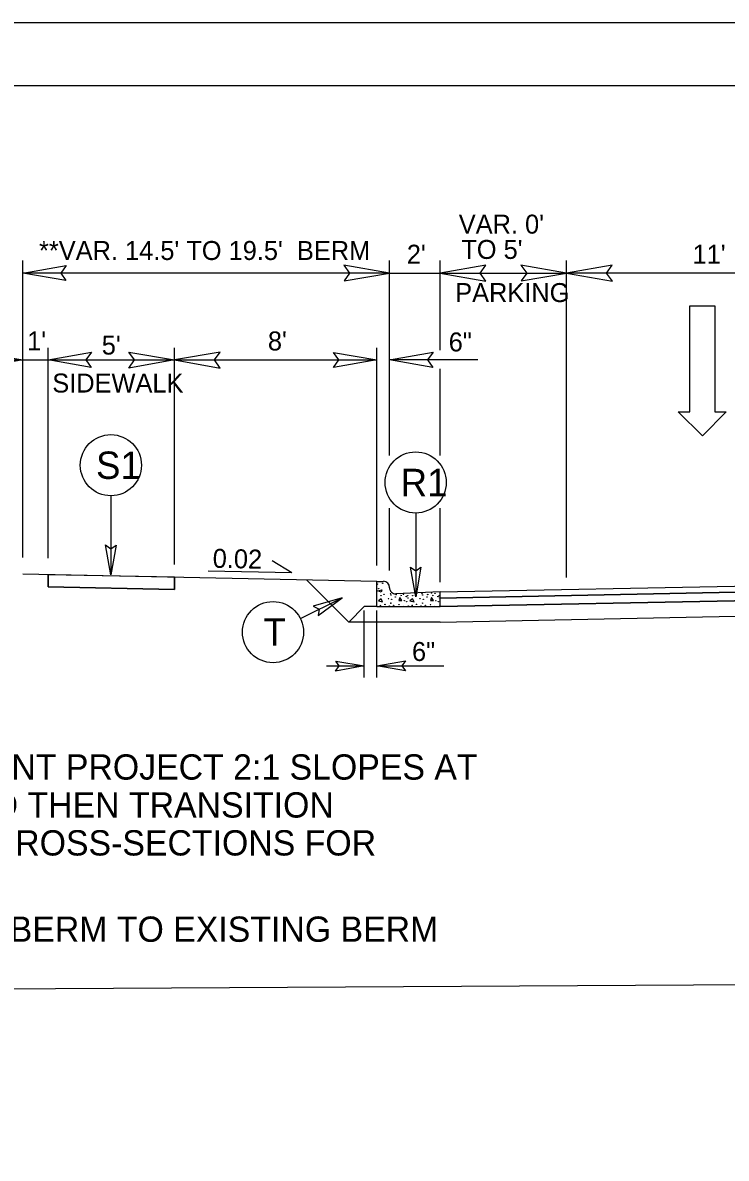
# Model space of a CAD drawing. Extents: x 1487909 to 1489267, y 497866 to 499814.
# Drawn here: x 1488931.46 to 1488959.27, y 498292.62 to 498337.52 of the extents above; entities that cross this region are included whole.
import ezdxf

# ---------------------------------------------------------------- set-up
doc = ezdxf.new("R2010")
doc.units = 0
for name, color, linetype in [('Old_Level_10', 7, 'Continuous'), ('Prop Conc 4in Sidewalk', 7, 'Continuous'), ('Prop Dimension', 7, 'Continuous'), ('Prop Dimension Text', 7, 'Continuous'), ('Prop DSN Text', 7, 'Continuous'), ('Prop Lane Arrow CELL', 7, 'Continuous'), ('Prop Shade Light', 7, 'Continuous'), ('Prop Terminator CELL', 7, 'Continuous'), ('Scratch_Level_1', 7, 'Continuous'), ('Sheet Plot Border Outside CELL', 7, 'Continuous'), ('Sheet Typical CELL', 7, 'Continuous'), ('Typical Curb CELL', 7, 'Continuous'), ('Typical Hinge Slope Arterial CELL', 7, 'Continuous'), ('Typical ID Circle CELL', 7, 'Continuous'), ('Typical Pavement Slope CELL', 7, 'Continuous'), ('Typical Pavement Slope Information CELL', 7, 'Continuous'), ('Typical Terminator CELL', 7, 'Continuous'), ('Typical Text ID Circle CELL', 7, 'Continuous')]:
    doc.layers.add(name, color=color, linetype=linetype)

msp = doc.modelspace()

# ---------------------------------------------------------------- linework, layer by layer
at = {"layer": 'Old_Level_10'}
for p, q in [((1488947.963, 498314.766), (1488974.964, 498315.306)), ((1488967.463, 498314.823), (1488947.963, 498314.433)), ((1488947.963, 498314.433), (1488947.963, 498314.766))]:
    msp.add_line(p, q, dxfattribs=at)
at = {"layer": 'Prop Conc 4in Sidewalk'}
for p, q in [((1488937.464, 498315.593), (1488932.464, 498315.693)), ((1488932.464, 498315.212), (1488932.464, 498315.693)), ((1488937.464, 498315.112), (1488932.464, 498315.212)), ((1488937.464, 498315.593), (1488937.464, 498315.112))]:
    msp.add_line(p, q, dxfattribs=at)
at = {"layer": 'Prop Dimension'}
for p, q in [((1488931.464, 498316.375), (1488931.464, 498328.119)), ((1488945.964, 498320.407), (1488945.964, 498328.119)), ((1488947.964, 498324.577), (1488947.964, 498328.119)), ((1488952.964, 498315.587), (1488952.964, 498328.119)), ((1488945.964, 498327.619), (1488931.464, 498327.619)), ((1488945.964, 498327.619), (1488947.964, 498327.619)), ((1488947.964, 498327.619), (1488952.964, 498327.619)), ((1488963.964, 498327.619), (1488952.964, 498327.619)), ((1488932.464, 498316.345), (1488932.464, 498324.66)), ((1488937.464, 498316.097), (1488937.464, 498324.66)), ((1488945.464, 498316.054), (1488945.464, 498324.66)), ((1488929.133, 498324.188), (1488931.464, 498324.188)), ((1488931.464, 498324.188), (1488932.464, 498324.188)), ((1488932.464, 498324.188), (1488937.464, 498324.188)), ((1488937.464, 498324.188), (1488945.464, 498324.188)), ((1488949.459, 498324.188), (1488945.964, 498324.188)), ((1488947.964, 498320.407), (1488947.964, 498323.84)), ((1488945.964, 498315.857), (1488945.964, 498318.327)), ((1488947.964, 498315.395), (1488947.964, 498318.327))]:
    msp.add_line(p, q, dxfattribs=at)
at = {"layer": 'Prop DSN Text'}
for p, q in [((1488944.964, 498311.627), (1488944.964, 498314.281)), ((1488945.464, 498311.627), (1488945.464, 498314.281)), ((1488943.477, 498312.087), (1488944.964, 498312.087)), ((1488945.464, 498312.087), (1488948.112, 498312.087))]:
    msp.add_line(p, q, dxfattribs=at)
at = {"layer": 'Prop Lane Arrow CELL'}
for p, q in [((1488957.827, 498322.131), (1488957.827, 498326.331)), ((1488957.827, 498326.331), (1488958.817, 498326.331)), ((1488958.817, 498326.331), (1488958.817, 498322.131)), ((1488958.337, 498321.186), (1488957.377, 498322.131)), ((1488957.377, 498322.131), (1488957.827, 498322.131)), ((1488959.267, 498322.131), (1488958.337, 498321.186)), ((1488958.817, 498322.131), (1488959.267, 498322.131))]:
    msp.add_line(p, q, dxfattribs=at)
at = {"layer": 'Prop Shade Light'}
for p, q in [((1488937.464, 498315.593), (1488932.464, 498315.693)), ((1488932.464, 498315.693), (1488932.464, 498315.212)), ((1488932.464, 498315.212), (1488937.464, 498315.112)), ((1488937.464, 498315.112), (1488937.464, 498315.593)), ((1488947.963, 498315.016), (1488974.964, 498315.556)), ((1488974.964, 498315.306), (1488947.963, 498314.766)), ((1488947.963, 498314.766), (1488947.963, 498315.016))]:
    msp.add_line(p, q, dxfattribs=at)
at = {"layer": 'Prop Terminator CELL'}
for points in [[(1488933.174, 498327.324), (1488931.464, 498327.619), (1488933.183, 498327.923), (1488932.965, 498327.619)], [(1488944.164, 498327.309), (1488945.964, 498327.619), (1488944.154, 498327.939), (1488944.384, 498327.619)], [(1488949.764, 498327.929), (1488947.964, 498327.619), (1488949.774, 498327.299), (1488949.544, 498327.619)], [(1488951.164, 498327.309), (1488952.964, 498327.619), (1488951.154, 498327.939), (1488951.384, 498327.619)], [(1488954.764, 498327.929), (1488952.964, 498327.619), (1488954.774, 498327.299), (1488954.544, 498327.619)], [(1488929.664, 498324.498), (1488931.464, 498324.188), (1488929.654, 498323.868), (1488929.884, 498324.188)], [(1488934.174, 498323.894), (1488932.464, 498324.188), (1488934.183, 498324.492), (1488933.965, 498324.188)], [(1488935.664, 498324.498), (1488937.464, 498324.188), (1488935.654, 498323.868), (1488935.884, 498324.188)], [(1488939.264, 498324.498), (1488937.464, 498324.188), (1488939.274, 498323.868), (1488939.044, 498324.188)], [(1488943.754, 498324.483), (1488945.464, 498324.188), (1488943.744, 498323.884), (1488943.963, 498324.188)], [(1488947.674, 498323.894), (1488945.964, 498324.188), (1488947.683, 498324.492), (1488947.465, 498324.188)]]:
    msp.add_lwpolyline(points, close=True, dxfattribs=at)
at = {"layer": 'Scratch_Level_1'}
msp.add_line((1488899.964, 498299.145), (1489049.964, 498300.02), dxfattribs=at)
at = {"layer": 'Sheet Plot Border Outside CELL'}
msp.add_lwpolyline([(1489051.664, 498337.52), (1488883.264, 498337.52), (1488883.264, 498227.52), (1489051.664, 498227.52)], close=True, dxfattribs=at)
at = {"layer": 'Sheet Typical CELL'}
msp.add_lwpolyline([(1489049.964, 498335.02), (1488899.964, 498335.02), (1488899.964, 498230.02), (1489049.964, 498230.02)], close=True, dxfattribs=at)
at = {"layer": 'Typical Curb CELL'}
for p, q in [((1488945.464, 498314.433), (1488945.464, 498315.433)), ((1488945.464, 498315.433), (1488945.724, 498315.433)), ((1488945.964, 498315.183), (1488945.964, 498315.194)), ((1488945.5, 498315.055), (1488945.654, 498315.1)), ((1488945.638, 498315.009), (1488945.5, 498315.055)), ((1488945.626, 498314.736), (1488945.523, 498314.661)), ((1488945.689, 498314.622), (1488945.626, 498314.736)), ((1488945.654, 498315.1), (1488945.638, 498315.009)), ((1488947.963, 498315.016), (1488946.213, 498314.944)), ((1488946.368, 498314.793), (1488946.333, 498314.679)), ((1488946.453, 498314.673), (1488946.368, 498314.793)), ((1488946.875, 498314.736), (1488946.772, 498314.661)), ((1488946.937, 498314.622), (1488946.875, 498314.736)), ((1488947.617, 498314.793), (1488947.582, 498314.679)), ((1488947.703, 498314.673), (1488947.617, 498314.793)), ((1488947.963, 498314.433), (1488947.963, 498315.016)), ((1488945.464, 498314.433), (1488947.963, 498314.433)), ((1488945.523, 498314.661), (1488945.689, 498314.622)), ((1488946.333, 498314.679), (1488946.453, 498314.673)), ((1488946.772, 498314.661), (1488946.937, 498314.622)), ((1488947.582, 498314.679), (1488947.703, 498314.673))]:
    msp.add_line(p, q, dxfattribs=at)
for centre in [(1488945.477, 498315.323), (1488945.529, 498315.14), (1488945.694, 498315.357), (1488945.626, 498314.867), (1488945.746, 498314.918), (1488945.922, 498314.753), (1488946.002, 498314.946), (1488946.019, 498314.896), (1488946.048, 498314.725), (1488946.196, 498314.81), (1488946.225, 498314.912), (1488946.419, 498314.873), (1488946.516, 498314.927), (1488946.625, 498314.833), (1488946.681, 498314.867), (1488946.698, 498314.77), (1488946.875, 498314.867), (1488946.995, 498314.918), (1488947.171, 498314.753), (1488947.251, 498314.946), (1488947.269, 498314.896), (1488947.297, 498314.725), (1488947.446, 498314.81), (1488947.474, 498314.912), (1488947.622, 498314.975), (1488947.668, 498314.873), (1488947.765, 498314.958), (1488947.874, 498314.833), (1488947.93, 498314.867), (1488947.947, 498314.77), (1488945.609, 498314.479), (1488945.78, 498314.519), (1488945.957, 498314.456), (1488946.014, 498314.57), (1488946.128, 498314.485), (1488946.333, 498314.508), (1488946.493, 498314.439), (1488946.545, 498314.673), (1488946.641, 498314.627), (1488946.704, 498314.462), (1488946.858, 498314.479), (1488947.029, 498314.519), (1488947.206, 498314.456), (1488947.263, 498314.57), (1488947.377, 498314.485), (1488947.583, 498314.508), (1488947.742, 498314.439), (1488947.794, 498314.673), (1488947.89, 498314.627), (1488947.953, 498314.462)]:
    msp.add_circle(centre, 0.00802, dxfattribs=at)
for centre, start, end in [((1488945.724, 498315.194), 0, 90), ((1488946.203, 498315.183), 180, 272.3845)]:
    msp.add_arc(centre, 0.24, start, end, dxfattribs=at)
at = {"layer": 'Typical ID Circle CELL'}
for p, q in [((1488934.949, 498318.817), (1488934.949, 498315.693)), ((1488946.996, 498318.133), (1488946.996, 498314.816)), ((1488942.439, 498313.963), (1488944.096, 498314.787))]:
    msp.add_line(p, q, dxfattribs=at)
for centre in [(1488934.949, 498320.025), (1488946.996, 498319.342), (1488941.357, 498313.425)]:
    msp.add_circle(centre, 1.208, dxfattribs=at)
at = {"layer": 'Typical Pavement Slope CELL'}
for p, q in [((1488945.464, 498315.433), (1488931.464, 498315.713)), ((1488942.682, 498315.489), (1488944.35, 498313.82)), ((1488947.963, 498315.016), (1488974.964, 498315.556)), ((1488947.963, 498314.766), (1488974.964, 498315.306)), ((1488947.963, 498314.433), (1488974.964, 498314.973)), ((1488944.964, 498314.433), (1488944.35, 498313.82)), ((1488945.464, 498314.433), (1488944.964, 498314.433)), ((1488947.963, 498313.82), (1488974.964, 498314.36)), ((1488947.963, 498313.82), (1488944.35, 498313.82))]:
    msp.add_line(p, q, dxfattribs=at)
at = {"layer": 'Typical Pavement Slope Information CELL'}
for q in [(1488941.321, 498316.242), (1488938.788, 498315.835)]:
    msp.add_line((1488942.104, 498315.769), q, dxfattribs=at)
at = {"layer": 'Typical Terminator CELL'}
for points in [[(1488935.151, 498316.865), (1488934.949, 498315.693), (1488934.741, 498316.872), (1488934.949, 498316.722)], [(1488935.151, 498316.865), (1488934.949, 498315.693), (1488934.741, 498316.872), (1488934.949, 498316.722)], [(1488947.197, 498315.988), (1488946.996, 498314.816), (1488946.787, 498315.994), (1488946.996, 498315.844)], [(1488947.197, 498315.988), (1488946.996, 498314.816), (1488946.787, 498315.994), (1488946.996, 498315.844)], [(1488943.137, 498314.085), (1488944.096, 498314.787), (1488942.948, 498314.449), (1488943.175, 498314.329)], [(1488943.839, 498312.28), (1488944.964, 498312.087), (1488943.833, 498311.887), (1488943.976, 498312.087)], [(1488946.589, 498311.893), (1488945.464, 498312.087), (1488946.595, 498312.287), (1488946.451, 498312.087)]]:
    msp.add_lwpolyline(points, close=True, dxfattribs=at)

# ---------------------------------------------------------------- texts
at = {"layer": 'Prop Dimension Text'}
for s, p in [("VAR. 0' ", (1488948.7, 498329.181)), ("**VAR. 14.5' TO 19.5'  BERM", (1488932.108, 498328.139)), ("2'", (1488946.647, 498327.992)), ("TO 5'", (1488948.8, 498328.181)), ("11'", (1488957.941, 498327.992)), ('PARKING', (1488948.559, 498326.475)), ("1'", (1488931.638, 498324.562)), ("5'", (1488934.588, 498324.399)), ("8'", (1488941.155, 498324.562)), ('6"', (1488948.302, 498324.524)), ('SIDEWALK', (1488932.633, 498322.899))]:
    msp.add_text(s, height=0.75, dxfattribs=at).set_placement(p)
at = {"layer": 'Prop DSN Text'}
msp.add_text('6"', height=0.75, dxfattribs=at).set_placement((1488946.851, 498312.285))
at = {"layer": 'Typical Hinge Slope Arterial CELL'}
for s, p in [('* NOTE:  MATCH ADJACENT PROJECT 2:1 SLOPES AT ', (1488914.892, 498307.594)), ('      -L- STA. 11+04.26 AND THEN TRANSITION ', (1488914.892, 498306.094)), ('      SLOPE TO 3:1.  SEE CROSS-SECTIONS FOR ', (1488914.892, 498304.594)), ('** NOTE:  TIE PROPOSED BERM TO EXISTING BERM', (1488914.305, 498301.182))]:
    msp.add_text(s, height=1, dxfattribs=at).set_placement(p)
at = {"layer": 'Typical Pavement Slope Information CELL'}
msp.add_text('0.02', height=0.75, rotation=358.8543, dxfattribs=at).set_placement((1488938.968, 498315.971))
at = {"layer": 'Typical Text ID Circle CELL'}
for s, height, p in [('S1', 1.0817, (1488934.362, 498319.484)), ('R1', 1.0817, (1488946.402, 498318.801)), ('T', 1.082, (1488940.981, 498312.884))]:
    msp.add_text(s, height=height, dxfattribs=at).set_placement(p)

doc.saveas('drawing.dxf')
